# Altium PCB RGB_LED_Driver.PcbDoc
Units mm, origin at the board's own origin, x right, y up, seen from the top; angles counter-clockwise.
Board outline 103.1 x 80.1 mm, 4 copper layers (Top Layer 1, GND, POWER, Bottom Layer 1), stack 1.586 mm thick; 81 components, 62 nets, 264 pads, 168 vias.
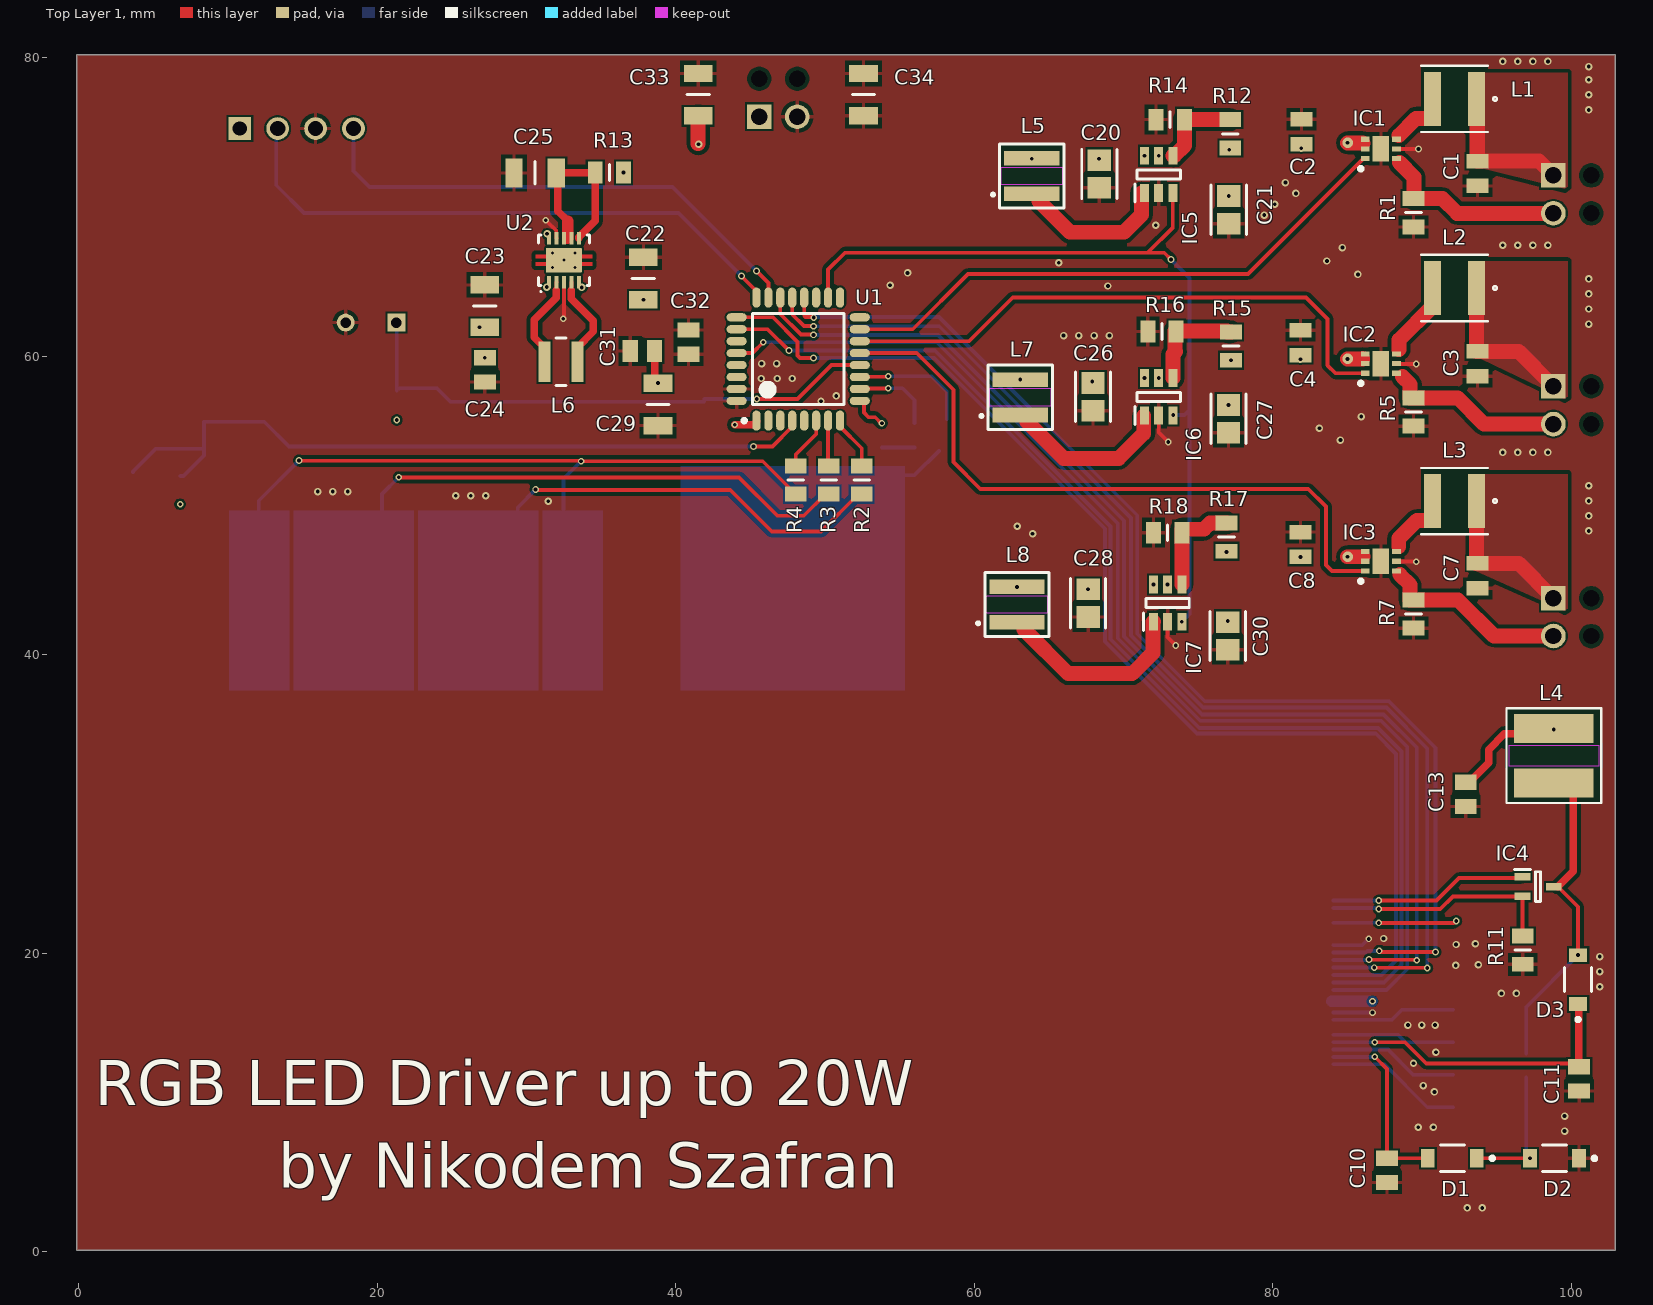
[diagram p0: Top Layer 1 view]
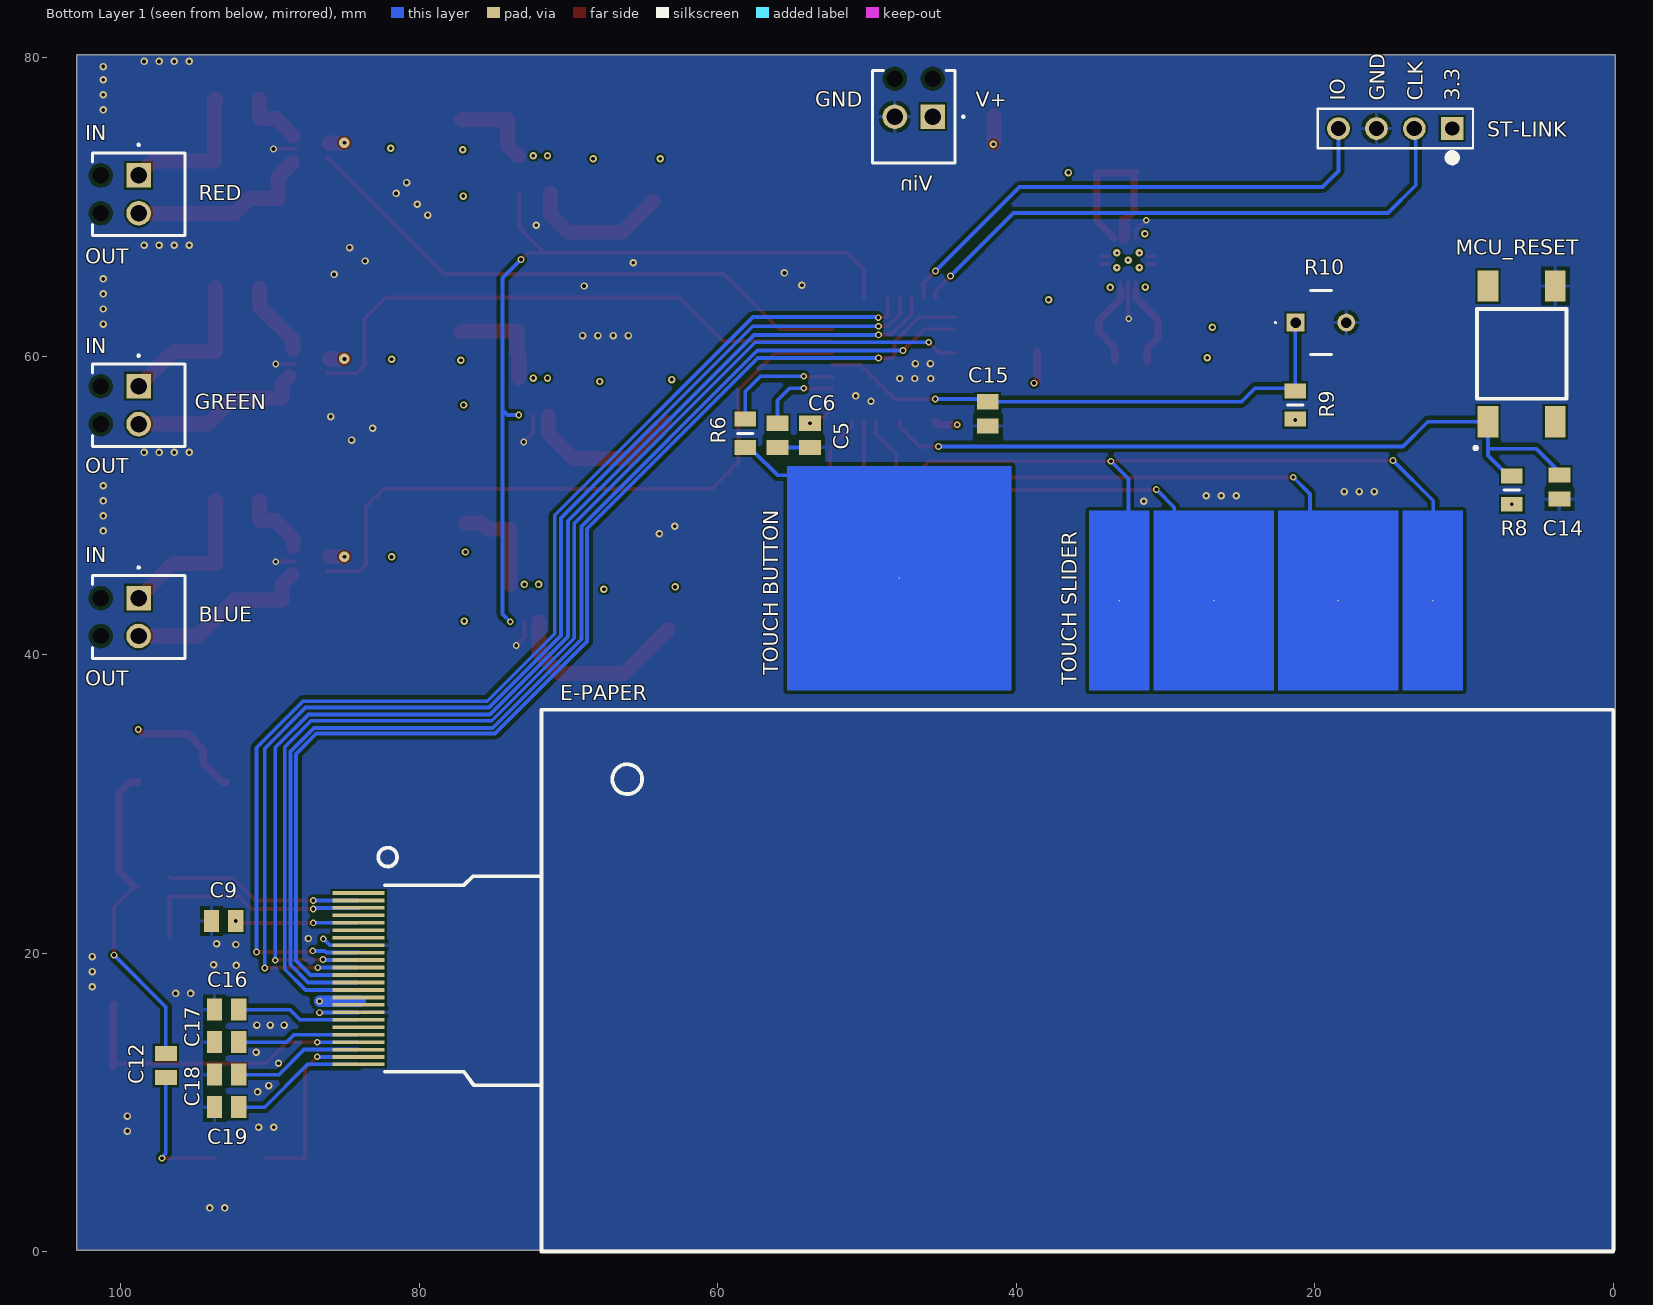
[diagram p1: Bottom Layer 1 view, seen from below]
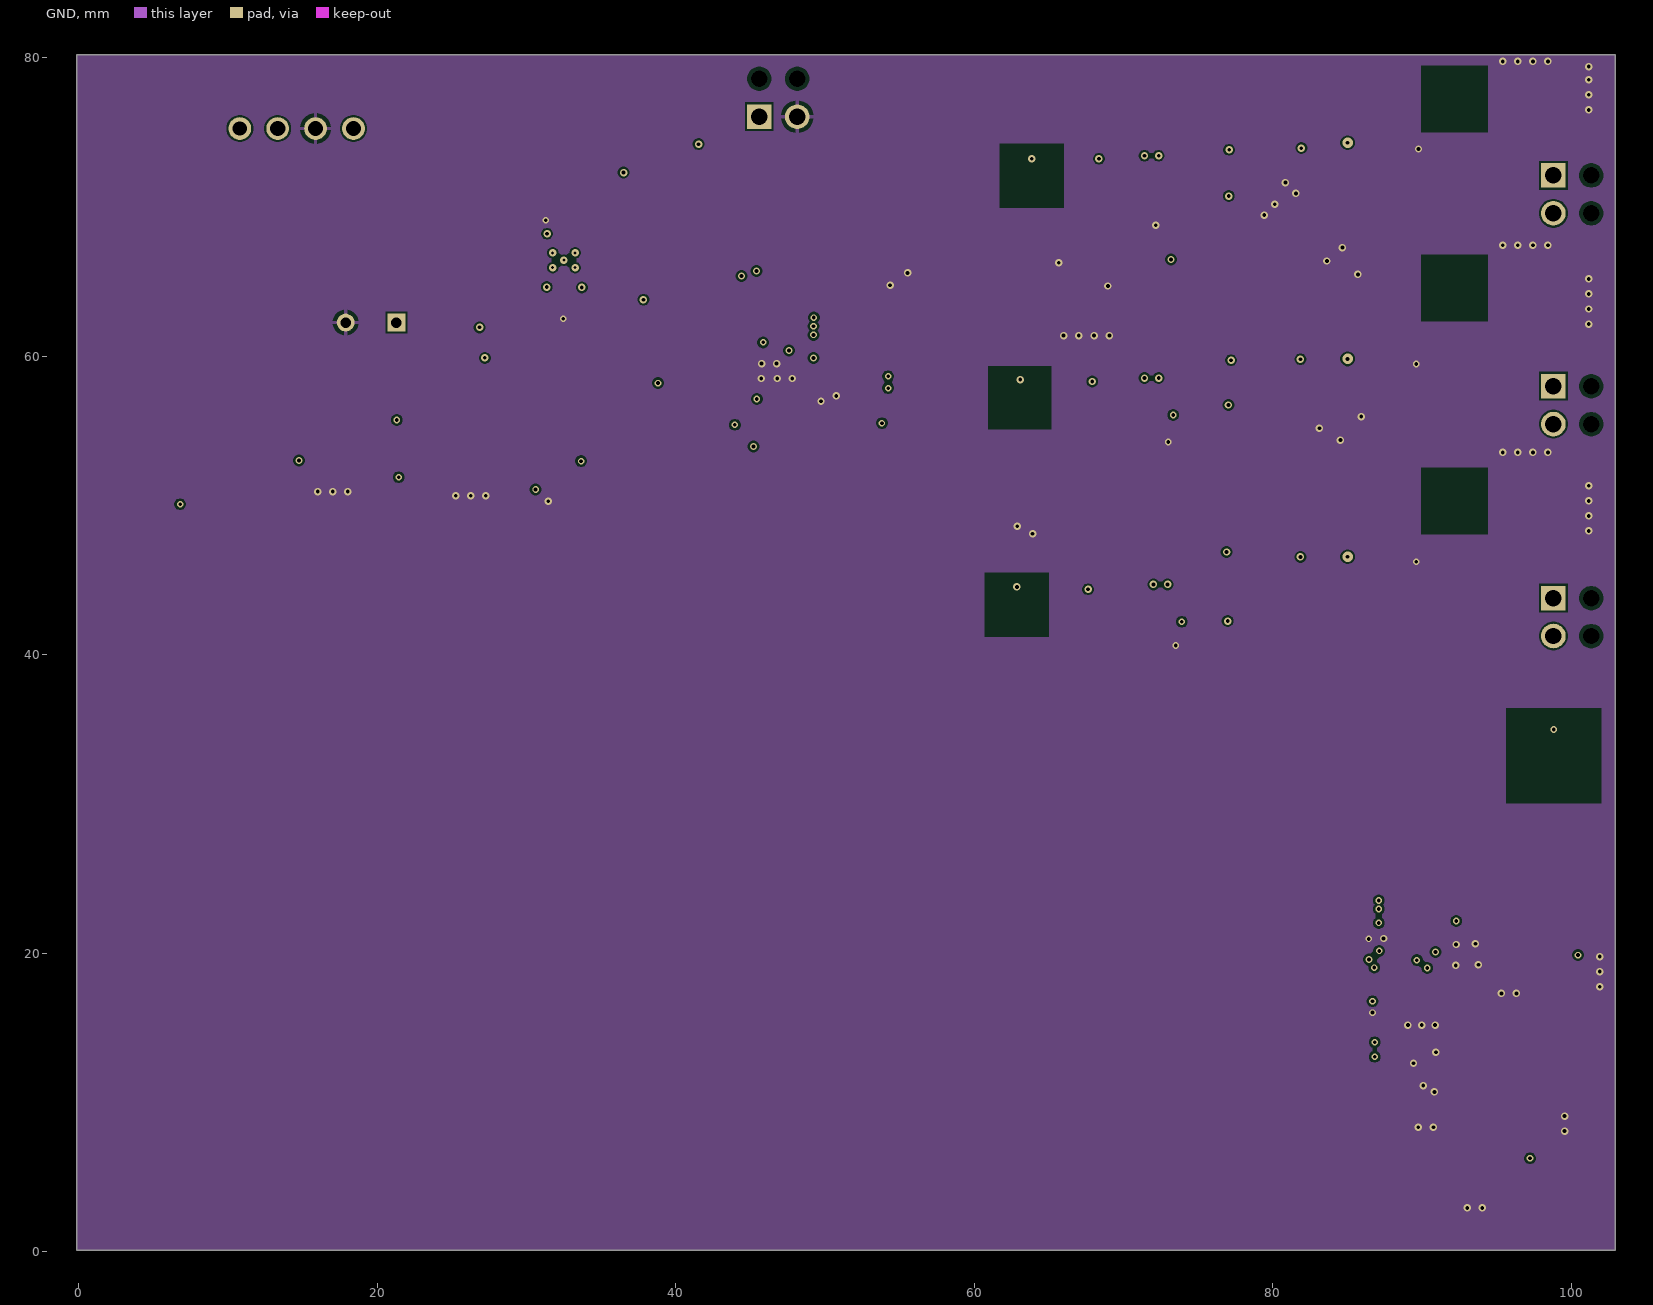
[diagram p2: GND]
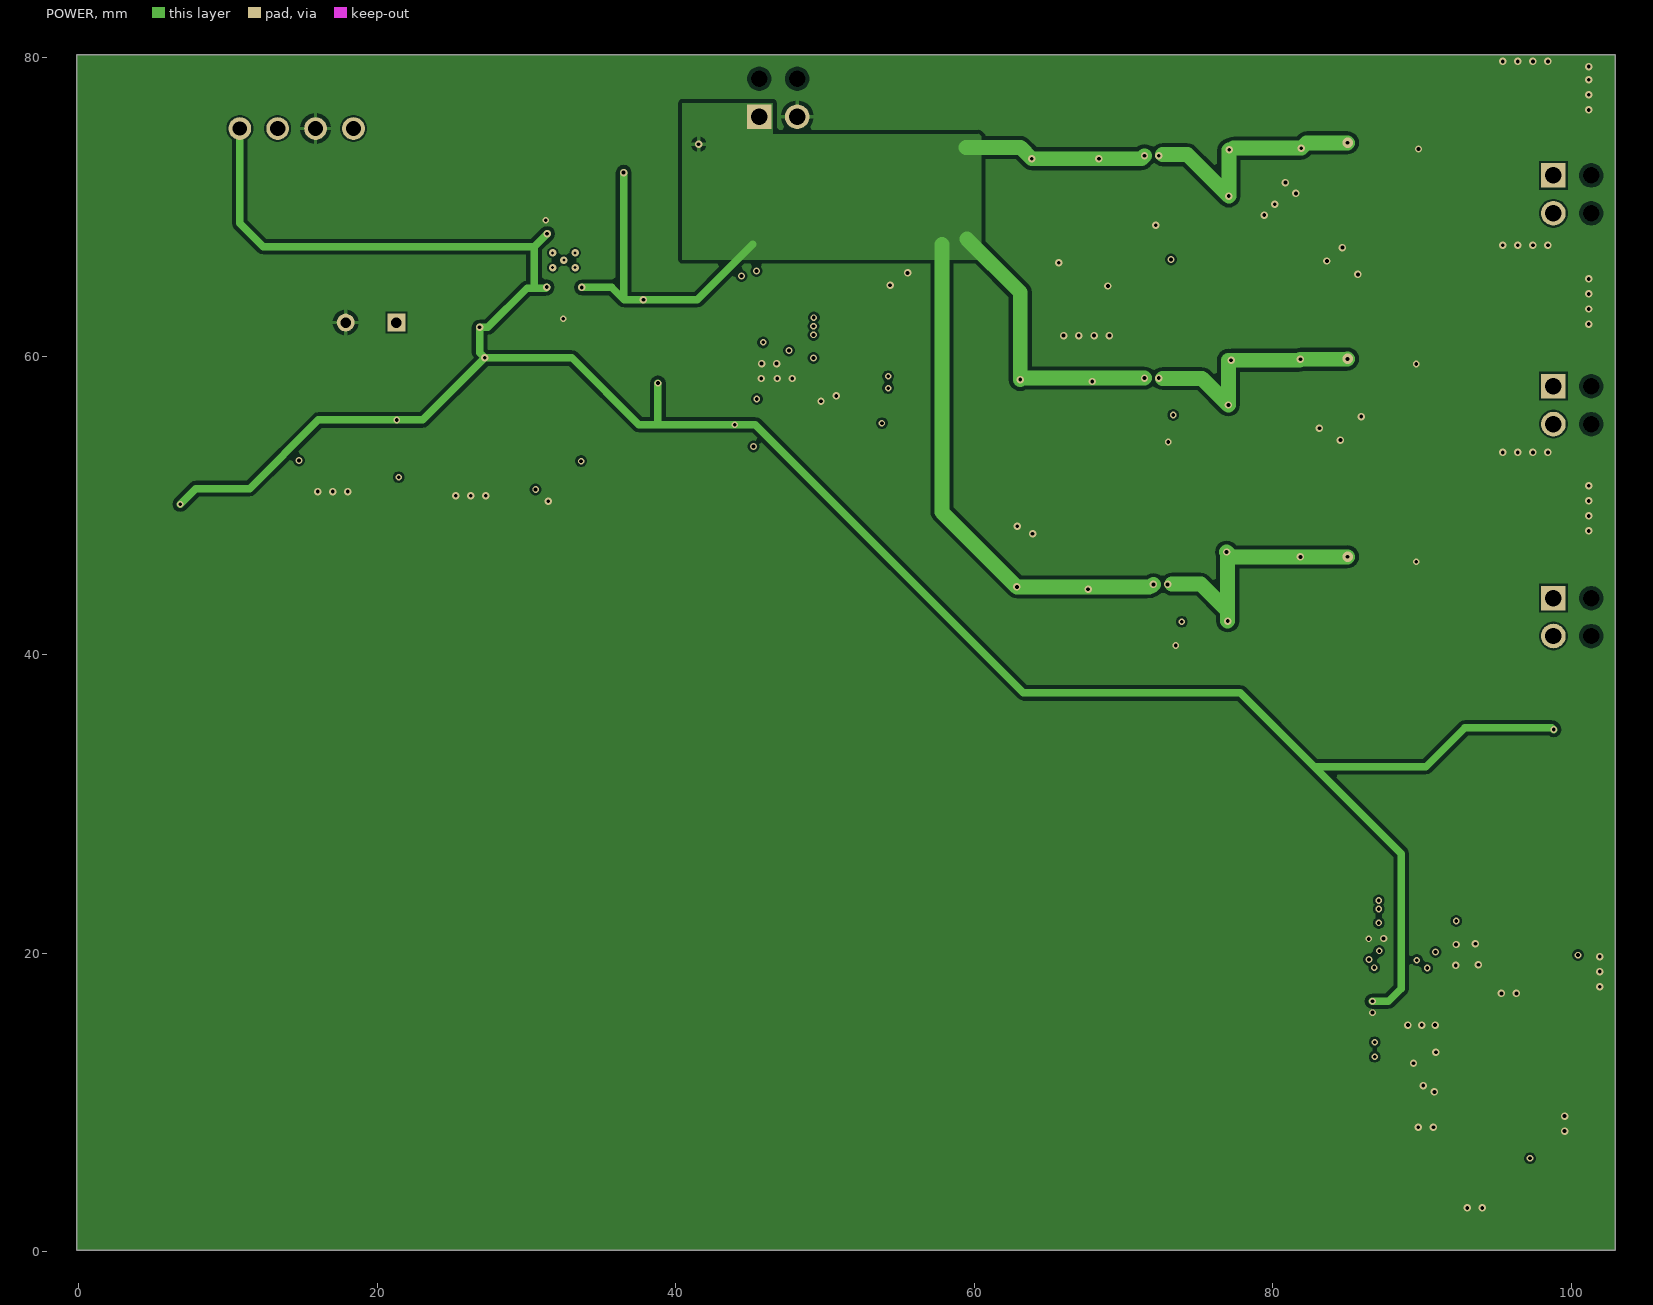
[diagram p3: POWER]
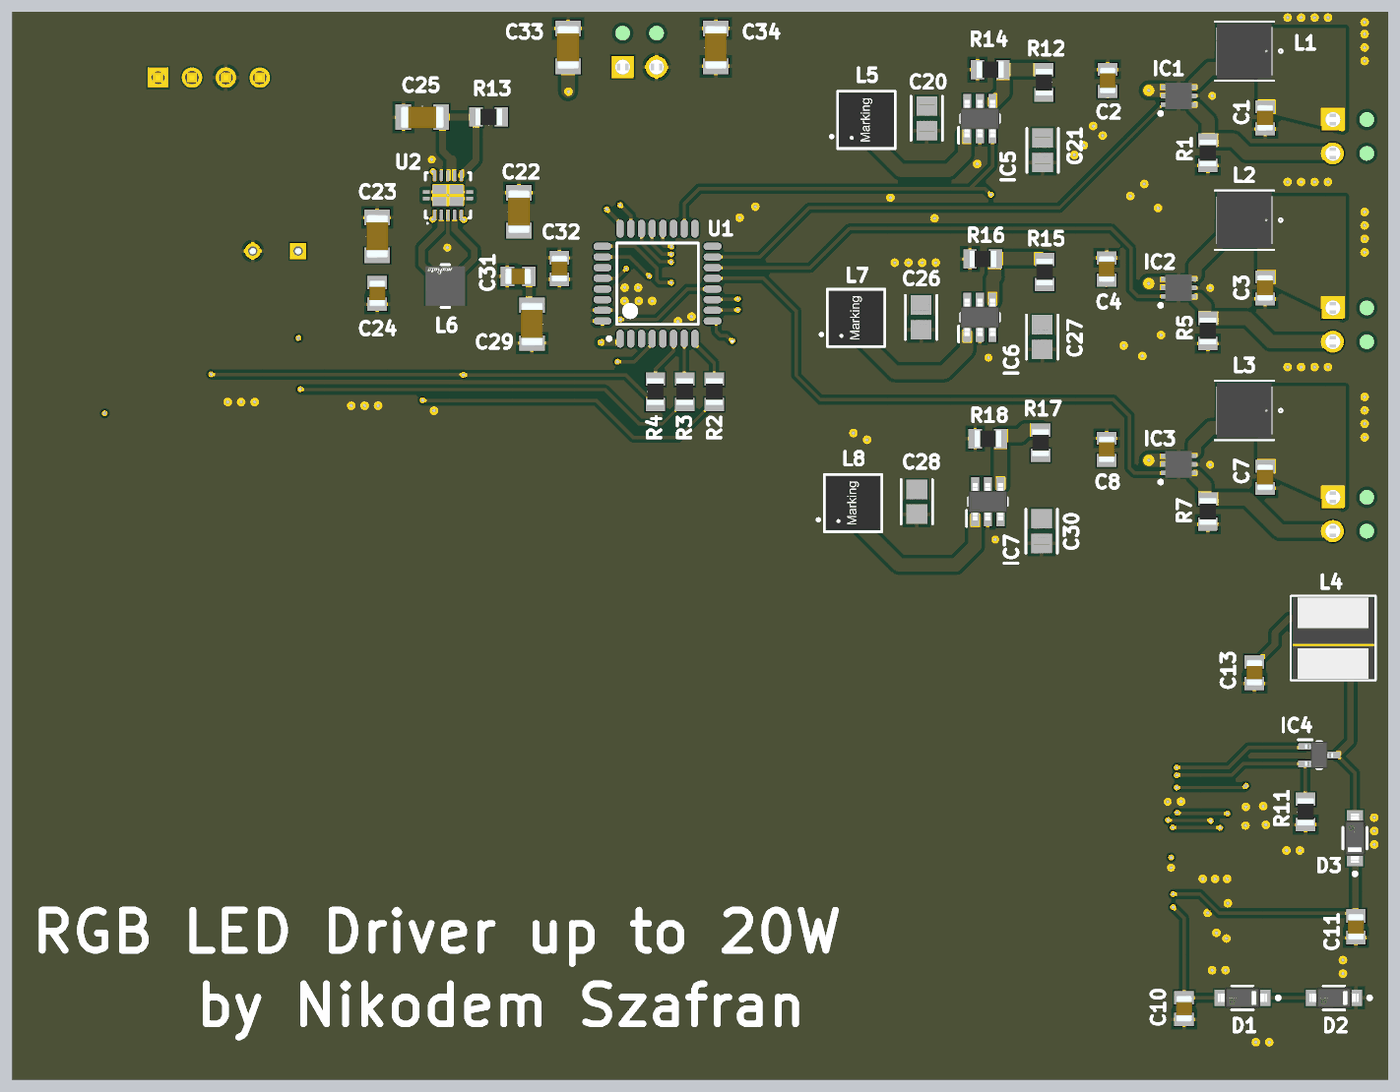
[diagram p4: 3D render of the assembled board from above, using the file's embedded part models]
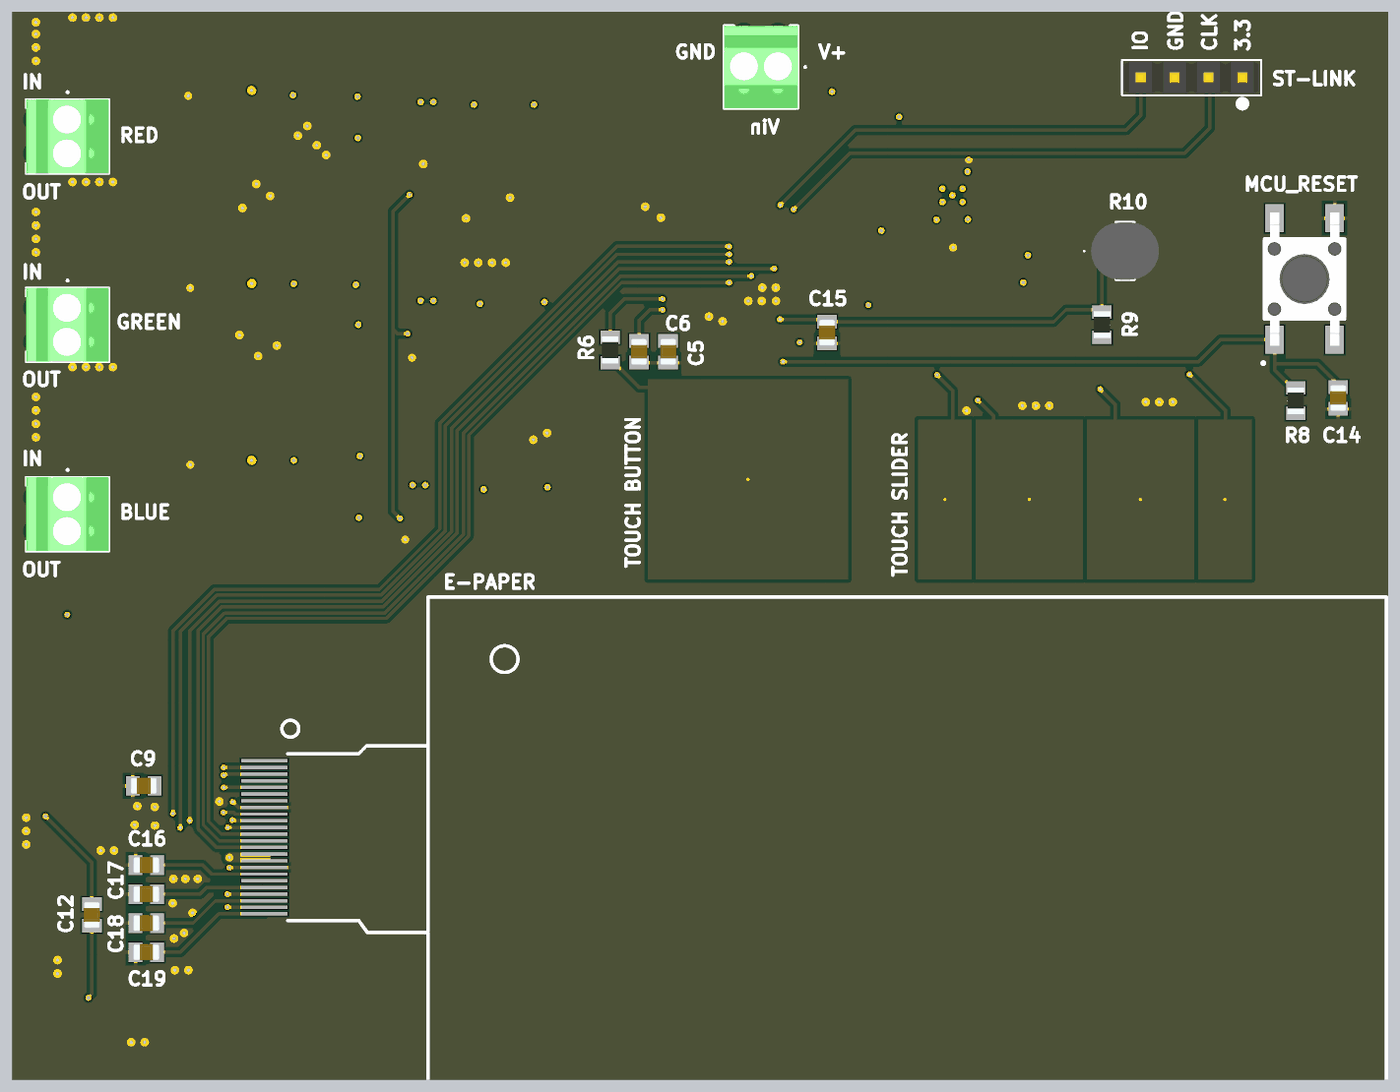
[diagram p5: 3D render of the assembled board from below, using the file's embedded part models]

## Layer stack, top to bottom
Top Solder: solder mask 0.0102, Solder Resist, Dk 3.5
Top Layer 1: signal copper 0.035
Dielectric 2: prepreg 0.2104, PP-006, Dk 4.1
GND: signal copper 0.0152
Dielectric 1: dielectric 1.065, FR-4, Dk 4.6
POWER: signal copper 0.0152
Dielectric 3: prepreg 0.2104, PP-006, Dk 4.1
Bottom Layer 1: signal copper 0.035
Bottom Solder: solder mask 0.0102, Solder Resist, Dk 3.5

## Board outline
-0.14,0.122 102.96,0.122 102.96,80.222 -0.14,80.222

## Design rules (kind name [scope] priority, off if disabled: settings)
Clearance [All] p1: gap=0.127 ignorepadtopadclearanceinfootprint=FALSE except(0.254: Arc-Fill Arc-Poly Arc-Region Track-Fill Track-Poly Track-Region Fill-Fill Fill-Poly Fill-Region Fill-Hole Poly-Poly Poly-Region Poly-Hole Region-Region Region-Hole)
HoleSize [All] p1: absolutevalues=TRUE maxlimit=2.54 minlimit=0.2 maxpercent=80.000 minpercent=20.000
HoleToHoleClearance [All] p1: gap=0.25 allowstackedmicrovias=TRUE
MinimumSolderMaskSliver [All] p1: minsoldermaskwidth=0.05
PolygonConnect PolygonConnect_7 [InNet('LED_R_IN') vs IsNamedPolygon('LED_R_IN_L01_P042')] p1: thpad.connectstyle=Direct thpad.reliefconductorwidth=0.254 thpad.reliefentries=4 thpad.polygonreliefangle="90 Angle" thpad.airgapwidth=0.254 smdpad.connectstyle=Direct smdpad.reliefconductorwidth=0.254 smdpad.reliefentries=4 smdpad.polygonreliefangle="90 Angle" smdpad.airgapwidth=0.254 via.connectstyle=Relief via.reliefconductorwidth=0.254 via.reliefentries=4 via.polygonreliefangle="90 Angle" via.airgapwidth=0.254
PolygonConnect PolygonConnect_6 [InNet('LED_G_IN') vs IsNamedPolygon('LED_G_IN_L01_P044')] p2: thpad.connectstyle=Direct thpad.reliefconductorwidth=0.254 thpad.reliefentries=4 thpad.polygonreliefangle="90 Angle" thpad.airgapwidth=0.254 smdpad.connectstyle=Direct smdpad.reliefconductorwidth=0.254 smdpad.reliefentries=4 smdpad.polygonreliefangle="90 Angle" smdpad.airgapwidth=0.254 via.connectstyle=Relief via.reliefconductorwidth=0.254 via.reliefentries=4 via.polygonreliefangle="90 Angle" via.airgapwidth=0.254
PolygonConnect PolygonConnect_5 [InNet('LED_B_IN') vs IsNamedPolygon('LED_B_IN_L01_P045')] p3: thpad.connectstyle=Direct thpad.reliefconductorwidth=0.254 thpad.reliefentries=4 thpad.polygonreliefangle="90 Angle" thpad.airgapwidth=0.254 smdpad.connectstyle=Direct smdpad.reliefconductorwidth=0.254 smdpad.reliefentries=4 smdpad.polygonreliefangle="90 Angle" smdpad.airgapwidth=0.254 via.connectstyle=Relief via.reliefconductorwidth=0.254 via.reliefentries=4 via.polygonreliefangle="90 Angle" via.airgapwidth=0.254
PolygonConnect PolygonConnect_4 [InNet('Vin') vs IsNamedPolygon('VIN_L03_P039')] p4: thpad.connectstyle=Direct thpad.reliefconductorwidth=0.254 thpad.reliefentries=4 thpad.polygonreliefangle="90 Angle" thpad.airgapwidth=0.254 smdpad.connectstyle=Direct smdpad.reliefconductorwidth=0.254 smdpad.reliefentries=4 smdpad.polygonreliefangle="90 Angle" smdpad.airgapwidth=0.254 via.connectstyle=Relief via.reliefconductorwidth=0.254 via.reliefentries=4 via.polygonreliefangle="90 Angle" via.airgapwidth=0.254
PolygonConnect PolygonConnect_3 [InNet('GND') vs IsNamedPolygon('GND_L03_P041') Or IsNamedPolygon('GND_L04_P040')] p5: thpad.connectstyle=Relief thpad.reliefconductorwidth=0.254 thpad.reliefentries=4 thpad.polygonreliefangle="90 Angle" thpad.airgapwidth=0.254 smdpad.connectstyle=Relief smdpad.reliefconductorwidth=0.254 smdpad.reliefentries=4 smdpad.polygonreliefangle="90 Angle" smdpad.airgapwidth=0.254 via.connectstyle=Direct via.reliefconductorwidth=0.254 via.reliefentries=4 via.polygonreliefangle="90 Angle" via.airgapwidth=0.254
PolygonConnect PolygonConnect_2 [InNet('GND') vs IsNamedPolygon('GND_L02_P043')] p6: thpad.connectstyle=Relief thpad.reliefconductorwidth=0.254 thpad.reliefentries=4 thpad.polygonreliefangle="90 Angle" thpad.airgapwidth=0.254 smdpad.connectstyle=Relief smdpad.reliefconductorwidth=0.254 smdpad.reliefentries=4 smdpad.polygonreliefangle="90 Angle" smdpad.airgapwidth=0.254 via.connectstyle=Direct via.reliefconductorwidth=0.254 via.reliefentries=4 via.polygonreliefangle="90 Angle" via.airgapwidth=0.254
PolygonConnect PolygonConnect_1 [InNet('GND') vs IsNamedPolygon('GND_L01_P046')] p7: thpad.connectstyle=Relief thpad.reliefconductorwidth=0.254 thpad.reliefentries=4 thpad.polygonreliefangle="90 Angle" thpad.airgapwidth=0.254 smdpad.connectstyle=Relief smdpad.reliefconductorwidth=0.254 smdpad.reliefentries=4 smdpad.polygonreliefangle="90 Angle" smdpad.airgapwidth=0.254 via.connectstyle=Direct via.reliefconductorwidth=0.254 via.reliefentries=4 via.polygonreliefangle="90 Angle" via.airgapwidth=0.254
PolygonConnect [All] p8: connectstyle=Relief reliefconductorwidth=0.254 reliefentries=4 polygonreliefangle="90 Angle" airgapwidth=0.254
RoutingVias [All] p1: holewidth=0.254 width=0.45 viastyle="Through Hole" minholewidth=0.2 minwidth=0.45 maxholewidth=0.4 maxwidth=0.65
SilkToSolderMaskClearance [IsPad] p1: minsilkscreentomaskgap=0.15 clearancetoexposedcopper=TRUE
SolderMaskExpansion [All] p1: expansion=0.07 istentingtop=FALSE
SupplyNets "Schematic Supply Nets_1" [InNet('GND')] p1: voltage=0.000
Width [All] p1: maxlimit=8 minlimit=0.102 preferedwidth=1 toplayer_maxwidth=1 toplayer_prefwidth=0.254 midlayer1_maxwidth=1 midlayer1_prefwidth=0.254 bottomlayer_maxwidth=1 bottomlayer_prefwidth=0.254 minimp=50.000000 maximp=50.000000 favimp=50.000000
26 further rules are at their usual default settings.

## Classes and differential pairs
component class logika_sch_ideowy: BLUE C1 C2 C3 C4 C5 C6 C7 C8 C9 C10 C11 C12 C13 C14 C15 C16 C17 C18 C19 D1 D2 D3 E-PAPER GREEN IC1 IC2 IC3 IC4 L1 L2 L3 L4 MCU_RESET R1 R2 R3 R4 R5 R6 R7 R8 R9 R10 R11 RED ST-LINK "TOUCH BUTTON" "TOUCH SLIDER" U1
component class Designator: C20 C21 C22 C23 C24 C25 C26 C27 C28 C29 C30 C31 C32 C33 C34 IC5 IC6 IC7 l L5 L6 L7 L8 R12 R13 R14 R15 R16 R17 R18 U2 Vin

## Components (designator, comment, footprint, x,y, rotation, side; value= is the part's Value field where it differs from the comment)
BLUE "1725656" 1725656 98.809,43.808 r270 bottom
C1 "GRM21BR71A106KE51L" CAPC2012X145N 93.729,72.256 r270 top
C2 "GRM21BR71A106KE51L" CAPC2012X145N 81.935,75.057 r90 top
C3 "GRM21BR71A106KE51L" CAPC2012X145N 93.729,59.506 r270 top
C4 "GRM21BR71A106KE51L" CAPC2012X145N 81.86,60.921 r90 top
C5 "Capacitor" Capacitor_0805 53.814,54.717 r90 bottom value=47n
C6 "Capacitor" Capacitor_0805 55.992,54.717 r90 bottom value=47n
C7 "GRM21BR71A106KE51L" CAPC2012X145N 93.729,45.307 r270 top
C8 "GRM21BR71A106KE51L" CAPC2012X145N 81.86,47.401 r90 top
C9 "Capacitor" Capacitor_0805 93.11,22.172 r180 bottom value=1u
C10 "Capacitor" Capacitor_0805 87.66,5.462 r90 top value=1u
C11 "Capacitor" Capacitor_0805 100.535,11.597 r270 top value=1u
C12 "Capacitor" Capacitor_0805 96.985,12.487 r270 bottom value=1u
C13 "Capacitor" Capacitor_0805 92.935,30.657 r90 top value=1u
C14 "Capacitor" Capacitor_0805 3.61,51.251 r90 bottom value=47n
C15 "Capacitor" Capacitor_0805 41.91,56.157 r90 bottom value=47n
C16 "Capacitor" Capacitor_0805 92.91,16.231 r180 bottom value=1u
C17 "Capacitor" Capacitor_0805 92.91,14.053 r180 bottom value=1u
C18 "Capacitor" Capacitor_0805 92.91,11.875 r180 bottom value=1u
C19 "Capacitor" Capacitor_0805 92.91,9.697 r180 bottom value=1u
C20 "CL21A106KAYNNNE" FP-CL21-IPC_A 68.385,72.221 r90 top
C21 "CL21A106KAYNNNE" FP-CL21-IPC_A 77.06,69.822 r270 top
C22 "Capacitor" Capacitor_1206 37.835,65.222 r270 top value=10u
C23 "Capacitor" Capacitor_1206 27.213,63.372 r270 top value=10u
C24 "Capacitor" Capacitor_0805 27.21,59.097 r90 top value=10u
C25 "Capacitor" Capacitor_1206 30.585,72.297 r0 top value=0.1u
C26 "CL21A106KAYNNNE" FP-CL21-IPC_A 67.96,57.296 r270 top
C27 "CL21A106KAYNNNE" FP-CL21-IPC_A 77.035,55.822 r270 top
C28 "CL21A106KAYNNNE" FP-CL21-IPC_A 67.635,43.472 r270 top
C29 "Capacitor" Capacitor_1206 38.81,56.792 r270 top value=10u
C30 "CL21A106KAYNNNE" FP-CL21-IPC_A 76.985,41.272 r270 top
C31 "Capacitor" Capacitor_0805 37.77,60.372 r0 top value=100n
C32 "Capacitor" Capacitor_0805 40.86,60.957 r90 top value=100n
C33 "Capacitor" Capacitor_1206 41.507,77.54 r270 top value=10u
C34 "Capacitor" Capacitor_1206 52.581,77.54 r270 top value=10u
D1 "MBR0530" FP-425-04-MFG 92.035,6.272 r180 top
D2 "MBR0530" FP-425-04-MFG 98.885,6.272 r180 top
D3 "MBR0530" FP-425-04-MFG 100.46,18.247 r90 top
E-PAPER "18401 Waveshare" "18401 WAVESHARE" 35.91,18.172 r270 bottom
GREEN "1725656" 1725656 98.809,58.007 r270 bottom
IC1 "TPS92201ADRVR" SON65P200X200X80-7N 87.252,73.907 r0 top
IC2 "TPS92201ADRVR" SON65P200X200X80-7N 87.252,59.521 r0 top
IC3 "TPS92201ADRVR" SON65P200X200X80-7N 87.252,46.272 r0 top
IC4 "SI1304BDL-T1-E3" SOT65P210X110-3N 97.785,24.472 r0 top
IC5 "TLV61070ADBVR" SOT95P280X145-6N 72.36,72.197 r90 top
IC6 "TLV61070ADBVR" SOT95P280X145-6N 72.36,57.297 r90 top
IC7 "" SOT95P280X145-6N 72.96,43.472 r90 top
L1 "SDER041H-2R2MS" IND_SDER041H_CYN 92.18,77.26 r180 top value=2.2uH
L2 "SDER041H-2R2MS" IND_SDER041H_CYN 92.18,64.586 r180 top value=2.2uH
L3 "SDER041H-2R2MS" IND_SDER041H_CYN 92.18,50.311 r180 top value=2.2uH
L4 "SRR5018-470Y" IND_BOURNS_SRR5018 98.835,33.25 r90 top
L5 "74438357022" WE-MAPI_4030 63.86,72.099 r90 top
L6 "LQH3NPN2R2MMEL" FP-LQH3NPH_ME-MFG 32.31,59.647 r180 top
L7 "74438357022" WE-MAPI_4030 63.085,57.262 r90 top
L8 "74438357022" WE-MAPI_4030 62.86,43.372 r90 top
MCU_RESET "FSM4JSMATR" FSM4JSMATR 6.135,60.172 r0 bottom (schematic designator S1)
R1 "Resistor" Resistor_0805 89.437,69.63 r90 top value=75m
R2 "Resistor" Resistor_0805 52.46,51.722 r90 top value=1K (schematic designator R4)
R3 "Resistor" Resistor_0805 50.252,51.722 r90 top value=1K
R4 "Resistor" Resistor_0805 48.044,51.722 r90 top value=1K (schematic designator R2)
R5 "Resistor" Resistor_0805 89.437,56.28 r90 top value=75m
R6 "Resistor" Resistor_0805 58.16,54.847 r90 bottom value=1K
R7 "Resistor" Resistor_0805 89.437,42.742 r90 top value=75m
R8 "Resistor" Resistor_0805 6.796,51.047 r270 bottom value=10K
R9 "Resistor" Resistor_0805 21.31,56.747 r270 bottom value=1.5M
R10 "PGM5659D" PGM5659D 21.285,62.272 r180 bottom
R11 "Resistor" Resistor_0805 96.76,20.222 r90 top value=2.2
R12 "Resistor" Resistor_0805 77.16,74.922 r270 top value=820k
R13 "Resistor" Resistor_0805 35.56,72.322 r0 top value=100
R14 "Resistor" Resistor_0805 73.135,75.872 r0 top value=82k
R15 "Resistor" Resistor_0805 77.21,60.697 r270 top value=820k
R16 "Resistor" Resistor_0805 72.585,61.672 r0 top value=82k
R17 "Resistor" Resistor_0805 76.91,47.897 r270 top value=820k
R18 "Resistor" Resistor_0805 72.96,48.197 r0 top value=82k
RED "1725656" 1725656 98.809,72.129 r270 bottom
ST-LINK "77311-118-04LF" 77311-118-04LF_AMP 10.79,75.272 r180 bottom
"TOUCH BUTTON" "QTouch Button" ?#1 47.835,45.147 r180 bottom (schematic designator CS2)
"TOUCH SLIDER" "Small QTouch Slider" ?#2 22.596,43.647 r0 bottom (schematic designator CS1)
U1 "STM32F051K6T6" STM-LQFP32_L 48.21,59.822 r90 top
U2 "TPS63001DRCT" DRC0010J_V 32.51,66.447 r90 top
Vin "1725656" 1725656 45.596,76.066 r0 bottom

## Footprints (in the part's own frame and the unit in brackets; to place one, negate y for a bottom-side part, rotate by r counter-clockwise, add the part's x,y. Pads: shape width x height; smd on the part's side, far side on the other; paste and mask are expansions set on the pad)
"18401 WAVESHARE" [mm] "2.66 inch e-Paper display. Display resolution 296*152px"
  rect 0.25x3.5 smd: 1(-5.881,-48.16) 2(-5.381,-48.16) 3(-4.881,-48.16) 4(-4.381,-48.16) 5(-3.881,-48.16) 6(-3.381,-48.16) 7(-2.881,-48.16) 8(-2.381,-48.16) 9(-1.881,-48.16) 10(-1.381,-48.16) 11(-0.881,-48.16) 12(-0.381,-48.16) 13(0.119,-48.16) 14(0.619,-48.16) 15(1.119,-48.16) 16(1.619,-48.16) 17(2.119,-48.16) 18(2.619,-48.16) 19(3.119,-48.16) 20(3.619,-48.16) 21(4.119,-48.16) 22(4.619,-48.16) 23(5.111,-48.16) 24(5.6,-48.16)
  silkscreen extent -18.15,-46.84 18.15,35.91
77311-118-04LF_AMP [mil]
  rect 60x60 / inner round 60 / far side rect 60x60 hole 38 paste-99999 mask+0: 1(0,0)
  round 60 hole 40 paste-99999 mask+0: 2(-100,0) 3(-200,0) 4(-300,0)
  silkscreen extent -355,-87 55,52, body extent -350,-47 50,47, height 350
1725656 [mm]
  rect 1.65x1.65 hole 1.1: 1(0,0)
  round 1.65 hole 1.1: 2(2.54,0)
  round 0.55 hole 1.1 unplated: MH1(0,-2.54) MH2(2.54,-2.54)
  silkscreen extent -2.1,-3.1 4.04,3.1, body extent -1.5,-3.1 4.04,3.1, height 9
Capacitor_0805 [mm] "CAPC2012X152N"
  rect 1.02x1.47 smd: 1(-0.81,0) 2(0.81,0)
  body extent -1,-0.63 1,0.63, height 1.52
Capacitor_1206 [mm] "CAPC3317X180N,  / footprint from 1206GC102KAT1A"
  rect 1.17x1.92 smd: 1(-1.42,0) 2(1.42,0)
  silkscreen extent 0,-0.75 0,0.75, body extent -1.65,-0.85 1.65,0.85, height 1.8
CAPC2012X145N [mm]
  rect 0.97x1.47 smd: 1(-0.83,0) 2(0.83,0)
  body extent -1,-0.63 1,0.63, height 1.45
DRC0010J_V [mm] "SON, 10-Leads, Body 3x3mm, Pitch 0.5mm, Thermal Pad 2.4x1.65mm, TI Recommended"
  rrect36% 0.85x0.28 smd paste-0.025 mask+0.07: 1(-1.475,1) 2(-1.475,0.5) 3(-1.475,0) 4(-1.475,-0.5) 5(-1.475,-1) 6(1.475,-1) 7(1.475,-0.5) 8(1.475,0) 9(1.475,0.5) 10(1.475,1)
  rrect6% 1.65x2.4 smd paste-0.825 mask+0.07: 11(0,0)
  Top Layer 1 region: -0.39,1.2 -0.11,1.2 -0.11,1.9 -0.39,1.9
  Top Layer 1 region: 0.39,1.9 0.11,1.9 0.11,1.2 0.39,1.2
  Top Layer 1 region: 0.39,-1.2 0.11,-1.2 0.11,-1.9 0.39,-1.9
  Top Layer 1 region: -0.39,-1.9 -0.11,-1.9 -0.11,-1.2 -0.39,-1.2
  silkscreen extent -2.15,-1.7 1.7,1.7, body extent -1.55,-1.55 1.55,1.55, height 1
FP-425-04-MFG [mil]
  rect 36x48 smd paste+0 mask+0: 1(-64.5,0) 2(64.5,0)
  silkscreen extent -110,-35 32,35, body extent -72,-31 72,31, height 53
FP-CL21-IPC_A [mm]
  rect 1.455x1.556 smd paste+0 mask+0: 1(-0.926,0) 2(0.926,0)
  silkscreen extent -1.65,-1.18 1.65,1.18, body extent -2.15,-1.28 2.15,1.28, height 0.25
FP-LQH3NPH_ME-MFG [mm]
  rect 0.8x2.7 smd paste+0 mask+0: 1(-1.1,0) 2(1.1,0)
  silkscreen extent -0.33,-1.6 0.33,1.6, body extent -1.7,-1.7 1.7,1.7, height 0.25
FSM4JSMATR [mm]
  rect 1.4x2.1 smd: 1(2.25,4.55) 2(2.25,-4.55) 3(-2.25,4.55) 4(-2.25,-4.55)
  silkscreen extent -3,-3 3.18,6.39, body extent -3,-5 3,5, height 5.13
IND_BOURNS_SRR5018 [mil]
  rect 76x209 smd paste+0 mask+0: 1(-72,0) 2(72,0)
  Top Layer 1 keep-out region: -27.5,-118 -27.5,118 27.5,118 27.5,-118
  silkscreen extent -125,-125 125,125, body extent -120,-120 120,120, height 79
IND_SDER041H_CYN [mil]
  rect 45x142 smd paste-22.5 mask+0: 1(-58.07,0) 2(58.07,0)
  silkscreen extent -112,-88 88,88, body extent -83,-83 83,83, height 71
PGM5659D [mm]
  rect 1.2x1.2 hole 0.7: 1(0,0)
  round 1.2 hole 0.7: 2(3.4,0)
  silkscreen extent -1.4,-2.15 2.4,2.15, body extent -0.84,-2.15 4.24,2.15, height 2.5
Resistor_0805 [mm] "RESC2012X60N, / footprint from CRCW08050000Z0EAHP"
  rect 1x1.45 smd: 1(-0.95,0) 2(0.95,0)
  silkscreen extent 0,-0.53 0,0.53, body extent -1,-0.63 1,0.63, height 0.6
SON65P200X200X80-7N [mm]
  rect 0.6x0.35 smd: 1(-1.05,-0.65) 2(-1.05,0) 3(-1.05,0.65) 4(1.05,0.65) 5(1.05,0) 6(1.05,-0.65)
  rect 1.1x1.7 smd: 7(0,0)
  silkscreen extent -1.47,-1.45 -1.22,-1.2, body extent -1,-1 1,1, height 0.8
SOT65P210X110-3N [mm]
  rect 1.05x0.5 smd: 1(-1.05,0.65) 2(-1.05,-0.65) 3(1.05,0)
  silkscreen extent -1.58,-1 0.18,1.15, body extent -1.05,-1 1.05,1, height 1.1
SOT95P280X145-6N [mm]
  rect 1.2x0.6 smd: 1(-1.25,0.95) 2(-1.25,0) 3(-1.25,-0.95) 4(1.25,-0.95) 5(1.25,0) 6(1.25,0.95)
  silkscreen extent -1.85,-1.45 0.3,1.6, body extent -1.4,-1.45 1.4,1.45, height 1.2
STM-LQFP32_L [mm] "QFP, 32-Leads, Body 7x7mm, Pitch 0.8mm, IPC High Density"
  oval 1.35x0.55 smd: 1(-4.125,2.8) 2(-4.125,2) 3(-4.125,1.2) 4(-4.125,0.4) 5(-4.125,-0.4) 6(-4.125,-1.2) 7(-4.125,-2) 8(-4.125,-2.8) 17(4.125,-2.8) 18(4.125,-2) 19(4.125,-1.2) 20(4.125,-0.4) 21(4.125,0.4) 22(4.125,1.2) 23(4.125,2) 24(4.125,2.8)
  oval 0.55x1.35 smd: 9(-2.8,-4.125) 10(-2,-4.125) 11(-1.2,-4.125) 12(-0.4,-4.125) 13(0.4,-4.125) 14(1.2,-4.125) 15(2,-4.125) 16(2.8,-4.125) 25(2.8,4.125) 26(2,4.125) 27(1.2,4.125) 28(0.4,4.125) 29(-0.4,4.125) 30(-1.2,4.125) 31(-2,4.125) 32(-2.8,4.125)
  silkscreen extent -4.25,-3.05 3.05,3.75, body extent -3.5,-3.5 3.5,3.5, height 1.6
WE-MAPI_4030 [mm] "SMT Shielded Power Inductor, body 4.1x4.1mm"
  rect 0.98x3.7 smd: 1(-1.185,0) 2(1.185,0)
  Top Layer 1 keep-out region: -0.595,2.05 0.595,2.05 0.595,-2.05 -0.595,-2.05
  silkscreen extent -2.15,-2.15 2.15,2.7, body extent -2.05,-2.05 2.05,2.05, height 3.1
?#1 [mm]
  round 0.1 smd paste-0.05: 1(0,0)
  Top Layer 1 region: -7.5,-7.5 -7.5,7.5 7.5,7.5 7.5,-7.5 -7.5,-7.5
?#2 [mm]
  round 0.1 smd paste-0.05: 1(-10.492,0) 1(10.492,0) 2(-4.167,0) 3(4.167,0)
  Top Layer 1 region: -12.5,6 -8.483,6 -8.483,-6 -12.5,-6 -12.5,6
  Top Layer 1 region: -8.183,6 -0.15,6 -0.15,-6 -8.183,-6 -8.183,6
  Top Layer 1 region: 0.15,6 8.183,6 8.183,-6 0.15,-6 0.15,6
  Top Layer 1 region: 8.483,6 12.5,6 12.5,-6 8.483,-6 8.483,6

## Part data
BLUE GREEN RED Vin: "2-pin screw terminal block Connector", Manufacturer_Name="Phoenix Contact", Mouser Part Number=651-1725656
C1 C2 C3 C4 C7 C8: "Capacitor, LED DRIVER", Capacitance=10uF, Manufacturer_Name="Murata Electronics", Mouser Part Number=81-GRM21BR71A106KE51
C9 C10 C11 C12 C17 C18 C19: "Capacitor X5R/X7R, 25V"
C13 C16: "Capacitor X5R/X7R, 6V/25V"
C20 C21 C26 C27 C28 C30: library part CMP-13271-002975-1, "CL21 Series 0805 10uF 25V ±10% Tolerance X5R Multilayer Ceramic Chip Capacitor", Capacitance=10uF, Case Code (Imperial)=0805, Case Code (Metric)=2012, Dielectric=X5R, Max Operating Temperature=85°C, Min Operating Temperature=-55°C, Package Quantity=1, Tolerance=10%, Voltage Rating=25V
D1 D2 D3: library part 1d6ec82d83fb6aee721767c19dac4b9, "DIODE SCHOTTKY 30V 500MA SOD123", Average Rectified Current=500mA, Forward Voltage=430mV, Max Forward Surge Current (Ifsm)=5.5A, Max Operating Temperature=150°C, Max Repetitive Reverse Voltage (Vrrm)=30V, Max Reverse Leakage Current=130uA, Min Operating Temperature=-65°C, Package Quantity=1
E-PAPER: "E-PAPER display", MPN=18401
IC1 IC2 IC3: "Integrated Circuit", Manufacturer_Name="Texas Instruments", Mouser Part Number=595-TPS92201ADRVR
IC4: "Integrated Circuit", Manufacturer_Name=Vishay, Mouser Part Number=781-SI1304BDL-E3
IC5 IC6: "Integrated Circuit", Manufacturer_Name="Texas Instruments", Mouser Part Number=595-TLV61070ADBVR
IC7: library part TLV61070ADBVR, "Integrated Circuit", Manufacturer_Name="Texas Instruments", Mouser Part Number=595-TLV61070ADBVR
L1 L2 L3: "Inductor, LED Driver", Mfr_Name=Cyntec
L4: "Inductor", Mfr_Name="Bourns Electronics"
L5 L7 L8: library part CMP-03913-81252529-2, "74438357022 Fixed Ind 2.2UH 5.2A 26 Mohm SMD", Ambient Temperature Range High=85°C, Ambient Temperature Range Low=-40°C, Current Rating=5.2A, DC Resistance (DCR)=22mΩ, Inductance=2.2µH, Inductance Tolerance=20%, Max Operating Temperature=125°C, Saturation Current=7A, Self Resonant Frequency=35MHz, Series Resistance=26mΩ, Test Frequency=100kHz
L6: library part CMP-06042-009066-1, "Wire Wound Ferrite Inductor for Power Lines 2.2μH ±20% 0.078Ω 2100mA 1212", Case Code (Imperial)=1212, Case Code (Metric)=3030, Current Rating=2.1A, DC Resistance (DCR)=78mR, Inductance=2.2uH, Max Operating Temperature=85°C, Min Operating Temperature=-40°C, Resistor Type=Wirewound, Saturation Current=1.8A, Self Resonant Frequency=60MHz, Test Frequency=1MHz, Tolerance=20%
MCU_RESET: "Switch", Manufacturer_Name="TE Connectivity", Mouser Part Number=506-FSM4JSMATR
R1 R5 R7: "Rsense"
R10: "Resistor", Manufacturer_Name="TOKEN ELECTRONICS INDUSTRY CO LTD"
R11: "Resistor 0805 1%"
ST-LINK: "4-pin male goldpin header", Mfr_Name="Amphenol ICC"
"TOUCH BUTTON": library part QTouchButton
"TOUCH SLIDER": library part SmallQTouchSlider
U1: library part CMP-0304-00023-2, "ARM Cortex-M0 32-bit MCU, 32 KB Flash, 4 KB Internal RAM, 25 I/Os, 32-pin LQFP, -40 to 85 degC, Tray", I/Os (High Current)=25, Operating Frequency(F) (Processor speed) (MHz)=48, Supply Voltage(Vcc) min (V)=2
U2: library part CMP-0345-00002-2, "Buck-Boost Voltage Converter with 1.8 to 5.5 V Input and 3.3 V Output, -40 to 85 degC, 10-Pin SON (DRC), Green (RoHS & no Sb/Br)", Dynamic Voltage Scaling=TRUE, Manufacturer="Texas Instruments", Switching Frequency(Max)(kHz)=1500

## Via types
v1: diameter 0.5, hole 0.254, Top Layer 1 to Bottom Layer 1, 111 vias
v2: diameter 0.45, hole 0.254, Top Layer 1 to Bottom Layer 1, 49 vias
v3: diameter 0.5, hole 0.2, Top Layer 1 to Bottom Layer 1, 5 vias
v4: diameter 0.7, hole 0.254, Top Layer 1 to Bottom Layer 1, 3 vias

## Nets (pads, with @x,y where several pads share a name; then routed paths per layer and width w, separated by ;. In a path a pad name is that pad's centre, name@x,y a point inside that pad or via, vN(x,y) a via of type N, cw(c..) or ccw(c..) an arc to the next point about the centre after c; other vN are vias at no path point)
ADC_FOTORESISTOR: C15.2 R9.1 R10.1 U1.12 | length 36.8
  Top Layer 1 w0.254: v2(45.435,57.147) 48.16,57.147 50.447,59.434 52.322,59.434 U1.12
  Bottom Layer 1 w0.254: R10.1 21.31,62.247 R9.1 ; R9.1@21.442,57.829 21.485,57.872 24.01,57.872 24.915,56.967 C15.2 ; C15.2@41.91,57.147 v2(45.435,57.147)
BUSY: E-PAPER.9 U1.20 | length 80.8
  Top Layer 1 w0.254: U1.20 48.61,62.721 48.693,62.638 49.216,62.638 v2(49.254,62.601) ; v2(87.135,20.172) 87.188,20.172 87.263,20.097 v2(90.91,20.097)
  Bottom Layer 1 w0.254: v2(49.254,62.601) 49.292,62.638 49.44,62.638 49.449,62.647 57.635,62.647 70.926,49.356 70.926,41.422 75.451,36.897 87.799,36.897 90.91,33.786 v2(90.91,20.097) ; E-PAPER.9 86.236,20.053 86.356,20.172 v2(87.135,20.172)
BUTTON_SAMP: C6.2 U1.10 | length 5.5
  Top Layer 1 w0.254: U1.10 52.36,57.847 54.21,57.847 v2(54.235,57.872)
  Bottom Layer 1 w0.254: v2(54.235,57.872) 55.185,57.872 55.992,57.065 C6.2
D/C#: E-PAPER.11 U1.21 | length 81.4
  Top Layer 1 w0.254: U1.21 47.81,62.822 48.585,62.047 49.212,62.047 v2(49.235,62.024) ; v2(86.81,19.047) 86.823,19.034 90.348,19.034 v2(90.36,19.022)
  Bottom Layer 1 w0.254: v2(49.235,62.024) 57.658,62.024 70.502,49.18 70.502,41.307 75.337,36.473 87.623,36.473 90.36,33.736 v2(90.36,19.022) ; E-PAPER.11 84.072,19.051 86.806,19.051 v2(86.81,19.047)
GDR: E-PAPER.2 IC4.1 | length 13.3
  Top Layer 1 w0.254: v2(87.11,23.547) 90.985,23.547 92.485,25.047 96.66,25.047 IC4.1
  Bottom Layer 1 w0.254: E-PAPER.2 84.072,23.551 87.106,23.551 v2(87.11,23.547)
GND: C1.2 C2.2 C3.2 C4.2 C5.1 C6.1 C7.2 C8.2 C9.1 C10.1 C11.2 C13.1 C14.1 C15.1 C16.1 C17.1 C18.1 C19.1 C20.1 C21.2 C22.1 C23.1 C24.1 C25.1 C26.2 C27.2 C28.2 C29.2 C30.2 C31.1 C32.1 C32.2 C33.1 C34.1 C34.2 D2.1 E-PAPER.8 E-PAPER.17 IC1.5 IC1.7 IC2.5 IC2.7 IC3.5 IC3.7 IC5.2 IC6.2 IC7.2 MCU_RESET.4 R1.1 R5.1 R7.1 R10.2 R11.1 R14.1 R16.1 R18.1 ST-LINK.3 U1.31 U1.32 U2.3 U2.9 Vin.2 | length 19.3
  Top Layer 1 w0.254: v2(31.296,69.132) 31.997,68.431 31.997,67.935 U2.9 ; v2@32.506,62.57 v2(32.465,62.528) 32.465,62.581 32.506,62.623 32.506,64.968 U2.3 ; IC6.2 72.36,54.916 v2(73.003,54.273) ; IC7.2 72.96,41.184 v2(73.511,40.633) ; IC3.5 88.315,46.259 89.602,46.259 v2(89.615,46.247) ; IC2.5 88.323,59.5 v2(89.62,59.5) ; IC1.5 v2(89.767,73.907)
  Bottom Layer 1 w0.254: C5.1 C6.1 ; E-PAPER.17 84.072,16.051 86.667,16.051 v2(86.685,16.032) ; E-PAPER.8 84.072,20.555 86.002,20.555 86.421,20.974 v2(86.44,20.974)
  other v1: 93.035,2.947 94.043,2.947 99.56,8.097 89.76,8.347 90.768,8.347 99.56,9.105 90.835,10.722 90.085,11.147 89.435,12.647 90.935,13.372 89.06,15.197 89.985,15.197 90.885,15.197 95.327,17.322 96.335,17.322 101.91,17.772 101.91,18.78 92.26,19.197 93.785,19.247 101.91,19.788 92.285,20.597 93.585,20.647 87.432,20.999 63.91,48.122 101.185,48.306 62.885,48.622 101.185,49.314 31.46,50.297 101.185,50.322 25.26,50.672 26.268,50.672 27.276,50.672 16.01,50.947 17.018,50.947 18.026,50.947 101.185,51.33 95.419,53.572 96.427,53.572 97.435,53.572 98.443,53.572 84.535,54.397 83.135,55.184 85.935,55.972 49.735,56.997 50.76,57.355 45.735,58.522 46.81,58.522 47.81,58.522 45.752,59.522 46.76,59.522 65.985,61.397 67.01,61.397 68.035,61.397 69.06,61.397 101.185,62.172 101.185,63.18 101.185,64.188 68.96,64.722 54.36,64.772 101.185,65.196 85.71,65.497 55.535,65.597 65.66,66.272 83.635,66.397 84.673,67.297 95.419,67.447 96.427,67.447 97.435,67.447 98.443,67.447 72.16,68.797 79.435,69.472 80.143,70.197 81.56,70.922 80.852,71.647 101.185,76.522 101.185,77.53 101.185,78.538 101.185,79.422 95.419,79.772 96.427,79.772 97.435,79.772 98.443,79.772
LED_B_IN: BLUE.1 C7.1 L3.1 | length 10.3
  Top Layer 1 w1: L3.1 93.655,46.152 93.67,46.137 C7.1 96.481,46.137 BLUE.1
LED_B_OUT: BLUE.2 IC3.6 R7.2 | length 12.6
  Top Layer 1 w1: 88.522,45.383 89.212,44.694 89.212,43.692 R7.2 92.408,43.692 94.831,41.268 BLUE.2
LED_G_IN: C3.1 GREEN.1 L2.1 | length 10.4
  Top Layer 1 w1: L2.1 93.655,60.351 93.67,60.336 C3.1 96.481,60.336 GREEN.1
LED_G_OUT: GREEN.2 IC2.6 R5.2 | length 12
  Top Layer 1 w1: 88.688,58.655 89.212,58.13 89.212,57.23 R5.2 92.398,57.23 94.161,55.467 GREEN.2
LED_R_IN: C1.1 L1.1 RED.1 | length 9.7
  Top Layer 1 w1: L1.1 93.727,77.189 93.727,75.104 93.729,75.101 C1.1 97.852,73.086 RED.1
LED_R_OUT: IC1.6 R1.2 RED.2 | length 12.6
  Top Layer 1 w1: 88.497,72.993 89.462,72.028 89.462,70.58 R1.2 91.367,70.58 92.358,69.589 RED.2
MCU_RESET: C14.2 MCU_RESET.1 R8.1 U1.4 | length 50.9
  Top Layer 1 w0.254: v2(45.21,53.972) 46.485,53.972 47.81,55.297 U1.4
  Bottom Layer 1 w0.254: C14.2@3.636,52.267 3.636,52.292 5.166,53.822 8.385,53.822 ; R8.1 7.021,51.997 8.385,53.361 8.385,53.822 ; v2(45.21,53.972) 14.085,53.972 12.435,55.622 MCU_RESET.1 8.385,53.822
NetC12_1: C12.1 D3.2 IC4.3 L4.1 | length 21.8
  Top Layer 1 w0.254: IC4.3 99.11,24.472 100.46,23.122 v2(100.46,19.885)
  Top Layer 1 w0.5: L4.1@98.835,31.497 99.382,31.497 100.135,30.744 100.135,25.497 IC4.3@99.11,24.472
  Bottom Layer 1 w0.254: C12.1 96.985,16.41 v2(100.46,19.885)
NetC12_2: C12.2 D1.1 D2.2 | length 9.1
  Top Layer 1 w0.254: D1.1 v2(97.247,6.272)
  Bottom Layer 1 w0.254: C12.2 96.985,6.587 97.247,6.325 v2(97.247,6.272)
NetC25_2: C25.2 R13.1 U2.6 U2.7 U2.8 | length 12.2
  Top Layer 1 w0.5: 32.769,69.081 32.11,69.741 32.11,72.192 C25.2 32.03,72.322 R13.1 34.61,69.087 33.51,67.987 U2.6
  Top Layer 1 w0.75: 32.769,67.913 32.769,69.081
NetIC1_4: IC1.4 L1.2 | length 4
  Top Layer 1 w1: 88.446,74.796 89.607,75.957 90.634,75.957 90.705,76.028 L1.2
NetIC2_4: IC2.4 L2.2 | length 5
  Top Layer 1 w1: 88.472,60.471 88.472,61.12 90.705,63.354 L2.2
NetIC3_4: IC3.4 L3.2 | length 4.6
  Top Layer 1 w1: 88.446,47.263 88.446,47.796 89.657,49.007 90.634,49.007 90.705,49.079 L3.2
NetIC5_1: IC5.1 L5.1 | length 9.7
  Top Layer 1 w1: 64.325,70.412 66.415,68.322 70.035,68.322 71.21,69.497 IC5.1@71.21,70.947
NetIC5_4: IC5.4 R12.1 R14.2 | length 5.9
  Top Layer 1 w1: IC5.4 73.41,73.447 74.085,74.122 R14.2 R12.1
NetIC6_1: IC6.1 L7.1 | length 10.7
  Top Layer 1 w1: L7.1@63.55,55.612 65.99,53.172 69.685,53.172 71.36,54.847 IC6.1@71.36,55.997
NetIC6_4: IC6.4 R15.1 R16.2 | length 7
  Top Layer 1 w1: IC6.4 73.31,60.147 73.485,60.322 73.46,60.347 73.46,61.697 76.935,61.697 76.985,61.647 R15.1
NetIC7_1: IC7.1 L8.1 | length 12.5
  Top Layer 1 w1: L8.1@63.343,41.704 66.3,38.747 70.585,38.747 71.985,40.147 71.985,42.197 IC7.1
NetIC7_4: IC7.4 R17.1 R18.2 | length 6.9
  Top Layer 1 w1: IC7.4 R18.2 73.91,48.422 75.385,48.422 75.81,48.847 R17.1
NetL6_1: L6.1 U2.4 | length 6.4
  Top Layer 1 w0.254: 33.01,64.447 U2.4
  Top Layer 1 w0.5: 33.01,64.447 33.01,63.872 34.485,62.397 34.485,61.672 33.41,60.597 L6.1
NetL6_2: L6.2 U2.2 | length 6.2
  Top Layer 1 w0.254: 32.002,64.447 32.002,64.964 U2.2
  Top Layer 1 w0.5: L6.2 31.21,60.597 30.535,61.272 30.535,62.472 32.002,63.939 32.002,64.447
NetR2_1: "TOUCH SLIDER.3" R2.1 | length 27
  Top Layer 1 w0.254: v2(30.613,51.083) 30.638,51.058 43.649,51.058 46.435,48.272 49.735,48.272 52.235,50.772 R2.1
  Bottom Layer 1 w0.254: 28.959,48.787 29.413,49.24 29.413,49.883 v2(30.613,51.083)
NetR3_1: "TOUCH SLIDER.2" R3.1 | length 33.3
  Top Layer 1 w0.254: v2(21.438,51.908) 21.463,51.883 44.249,51.883 46.81,49.322 48.577,49.322 50.027,50.772 R3.1
  Bottom Layer 1 w0.254: 20.313,49.533 20.313,50.783 v2(21.438,51.908)
NetR4_1: "TOUCH SLIDER.1" R4.1 | length 46
  Top Layer 1 w0.254: v2(14.763,53.033) 14.788,53.008 33.638,53.008 v2(33.663,52.983) 45.833,52.983 R4.1
  Bottom Layer 1 w0.254: 11.865,48.965 12.063,49.162 12.063,50.333 v2(14.763,53.033) ; 12.19,47.706 12.19,49.164 ; 32.488,48.456 32.488,51.808 v2(33.663,52.983)
NetR6_1: "TOUCH BUTTON.1" R6.1 | length 3.9
  Bottom Layer 1 w0.254: 54.41,51.997 54.46,52.047 56.01,52.047 R6.1@57.635,53.672
PWM_B: IC3.1 U1.13 | length 45
  Top Layer 1 w0.254: U1.13 56.153,60.222 58.61,57.764 58.61,52.922 60.41,51.122 82.385,51.122 83.569,49.938 83.569,46.018 83.965,45.622 IC3.1
PWM_G: IC2.1 U1.14 | length 39
  Top Layer 1 w0.254: U1.14 59.66,61.022 62.585,63.947 82.235,63.947 83.671,62.511 83.671,59.404 84.204,58.871 IC2.1
PWM_R: IC1.1 U1.15 | length 38.6
  Top Layer 1 w0.254: U1.15 55.885,61.822 59.585,65.522 78.342,65.522 86.077,73.257 IC1.1
RES#: E-PAPER.10 U1.22 | length 80.2
  Top Layer 1 w0.254: U1.22 47.01,62.847 48.385,61.472 49.21,61.472 v2(49.235,61.447) ; v2(86.46,19.599) 86.486,19.573 89.634,19.573 v2(89.66,19.547)
  Bottom Layer 1 w0.254: v2(49.235,61.447) 57.585,61.447 70.043,48.989 70.043,41.228 75.258,36.013 87.433,36.013 89.66,33.786 v2(89.66,19.547) ; E-PAPER.10 86.361,19.553 86.407,19.599 v2(86.46,19.599)
RESE: E-PAPER.3 IC4.2 R11.2 | length 15.7
  Top Layer 1 w0.254: v2(87.11,22.97) 91.233,22.97 92.085,23.822 IC4.2 96.735,21.197 R11.2
  Bottom Layer 1 w0.254: E-PAPER.3 86.974,23.053 87.057,22.97 v2(87.11,22.97)
SLIDER_SAMP: C5.2 U1.9 | length 2.5
  Top Layer 1 w0.254: U1.9 52.471,57.022 52.608,56.885 52.608,56.234 52.918,55.924 53.364,55.924 53.761,55.527 v2(53.814,55.527)
SPI_MISO: U1.27
SPI_MOSI: E-PAPER.14 U1.28 | length 81.4
  Top Layer 1 w0.254: U1.28 45.135,60.222 v2(45.86,60.947)
  Bottom Layer 1 w0.254: v2(45.86,60.947) 57.485,60.947 69.618,48.814 69.618,41.114 75.143,35.589 87.257,35.589 89.022,33.824 89.022,18.945 87.629,17.553 E-PAPER.14
SPI_NSS: E-PAPER.12 U1.25 | length 79.7
  Top Layer 1 w0.254: U1.25 46.51,62.622 48.16,60.972 48.16,60.072 48.335,59.897 v2(49.235,59.897)
  Bottom Layer 1 w0.254: v2(49.235,59.897) 57.321,59.897 68.76,48.458 68.76,40.894 74.924,34.731 86.901,34.731 88.26,33.372 88.26,19.522 87.291,18.553 E-PAPER.12
SPI_SCK: E-PAPER.13 U1.26 | length 80.1
  Top Layer 1 w0.254: U1.26 46.16,61.822 v2(47.585,60.397)
  Bottom Layer 1 w0.254: v2(47.585,60.397) 57.36,60.397 69.141,48.616 69.141,41.052 75.082,35.112 87.059,35.112 88.641,33.53 88.641,19.239 87.454,18.053 E-PAPER.13
SWDCLK: ST-LINK.2 U1.24 | length 39.4
  Top Layer 1 w0.254: v2(44.41,65.397) 44.41,65.372 45.41,64.372 U1.24
  Bottom Layer 1 w0.254: ST-LINK.2 13.235,75.177 13.235,71.472 15.096,69.611 40.196,69.611 v2(44.41,65.397)
SWDIO: ST-LINK.4 U1.23 | length 34.7
  Top Layer 1 w0.254: v2(45.41,65.722) 46.21,64.922 U1.23
  Bottom Layer 1 w0.254: ST-LINK.4 18.41,72.422 19.485,71.347 39.785,71.347 v2(45.41,65.722)
TSC_BUTTON: R6.2 U1.11 | length 8.1
  Top Layer 1 w0.254: U1.11 52.36,58.647 54.21,58.647 v2(54.235,58.672)
  Bottom Layer 1 w0.254: v2(54.235,58.672) 57.135,58.672 58.16,57.647 R6.2
TSC_SLIDER1: R4.2 U1.6 | length 3.6
  Top Layer 1 w0.254: R4.2 48.044,53.422 49.41,54.788 U1.6
TSC_SLIDER2: R3.2 U1.7 | length 3
  Top Layer 1 w0.254: U1.7 50.21,52.714 R3.2
TSC_SLIDER3: R2.2 U1.8 | length 3.6
  Top Layer 1 w0.254: U1.8 51.01,55.297 52.46,53.847 R2.2
TSCL: E-PAPER.6
TSDA: E-PAPER.7
V3.3: C13.2 C23.2 C24.2 C29.1 C31.2 E-PAPER.15 E-PAPER.16 L4.2 R8.2 R9.2 ST-LINK.1 U1.1 U2.1 U2.10 | length 183.9
  Top Layer 1 w0.5: C31.2@38.58,60.347 38.58,58.442 v2(38.81,58.212) ; v2(43.96,55.422) 45.185,55.422 U1.1@45.435,55.672 ; C13.2 93.16,31.467 94.472,32.779 94.472,33.654 95.524,34.706 98.539,34.706 v2(98.835,35.002)
  POWER w0.5: v2(6.796,50.097) 7.846,51.147 11.46,51.147 16.06,55.747 v2(21.31,55.747) 23.05,55.747 v1(27.21,59.907) ; ST-LINK.1 10.79,68.917 12.36,67.347 30.51,67.347 ; v1(31.36,64.647) 31.285,64.572 30.51,64.572 ; v1(31.385,68.222) 30.51,67.347 ; v2(38.81,58.212) 38.81,55.422 ; v2(86.685,16.797) 87.76,16.797 88.61,17.647 88.61,26.672 82.773,32.509 ; v2(98.835,35.002) 98.715,35.122 92.885,35.122 90.273,32.509 82.773,32.509 ; v1(27.21,59.907) 26.86,60.257 v1(26.86,61.952) 27.415,61.952 30.035,64.572 30.51,64.572 ; v1(27.21,59.907) 33.05,59.907 37.535,55.422 38.81,55.422 ; 30.51,64.572 30.51,67.347 ; 38.81,55.422 v2(43.96,55.422) 45.337,55.422 63.3,37.458 77.824,37.458 82.773,32.509
  Bottom Layer 1 w0.75: 83.96,16.797 v2(86.685,16.797)
V5.5_1: C2.1 C21.1 IC1.2 IC1.3 IC5.5 R12.2 | length 17.6
  Top Layer 1 w1: v4(85.017,74.314) 86.033,74.314 86.059,74.288
  POWER w1: 72.61,73.522 74.286,73.522 v1(77.06,70.748) 77.06,73.822 v1(77.085,73.847) ; 77.375,73.957 v1(81.92,73.957) 82.277,74.314 v4(85.017,74.314)
  other v1: 72.36,73.447
V5.5_2: C4.1 C27.1 IC2.2 IC2.3 IC6.5 R15.2 | length 16.9
  Top Layer 1 w1: v4(85.017,59.836) 86.008,59.836 86.033,59.861
  POWER w1: 72.61,58.522 75.261,58.522 v1(77.035,56.748) v1@77.035,59.747 ; v1(77.21,59.747) v1@81.795,59.747 ; v1(81.86,59.812) 84.993,59.812 v4(85.017,59.836)
  other v1: 72.36,58.547
V5.5_3: C8.1 C30.1 IC3.2 IC3.3 IC7.5 R17.2 | length 18.1
  Top Layer 1 w1: v4(85.017,46.577) 86.033,46.577 86.059,46.602
  POWER w1: 73.235,44.747 75.185,44.747 76.985,42.947 ; v1(76.91,46.897) 77.236,46.571 v1(81.86,46.571) 85.012,46.571 v4(85.017,46.577) ; v1(76.985,42.272) 76.985,42.947 ; 76.985,46.622 76.985,42.947
  other v1: 72.96,44.722
V5.5_EN: IC5.3 IC6.3 IC7.3 U1.18 | length 56.5
  Top Layer 1 w0.254: U1.18 50.21,65.822 51.335,66.947 71.61,66.947 ; v2(73.185,66.497) 72.735,66.947 71.61,66.947 ; IC5.3 73.31,68.647 71.61,66.947
  Bottom Layer 1 w0.254: v2(73.185,66.497) 74.435,65.247 74.435,56.422 ; v2(73.335,56.072) 74.085,56.072 74.435,56.422 ; v2(73.91,42.222) 74.435,42.747 74.435,56.422
VCOM: C19.2 E-PAPER.24 | length 9.2
  Bottom Layer 1 w0.254: E-PAPER.24 87.485,12.572 90.36,9.697 C19.2
VDD: C16.2 E-PAPER.18 | length 8.3
  Bottom Layer 1 w0.254: E-PAPER.18 87.991,15.553 88.669,16.231 C16.2
VGH: C11.1 D3.1 E-PAPER.21 | length 21.4
  Top Layer 1 w0.254: v2(86.835,14.047) 88.86,14.047 90.285,12.622 100.32,12.622 C11.1
  Top Layer 1 w0.5: D3.1 100.498,16.571 100.498,12.444 C11.1
  Bottom Layer 1 w0.254: E-PAPER.21 84.072,14.051 86.831,14.051 v2(86.835,14.047)
VGL: C10.2 D1.2 E-PAPER.23 | length 12.7
  Top Layer 1 w0.254: v2(86.835,13.074) 87.66,12.249 C10.2 D1.2
  Bottom Layer 1 w0.254: E-PAPER.23 84.072,13.063 86.824,13.063 v2(86.835,13.074)
Vin: C20.2 C22.2 C26.1 C28.1 C33.2 IC5.6 IC6.6 IC7.6 L5.2 L7.2 L8.2 R13.2 U2.5 Vin.1 | length 89.6
  Top Layer 1 w0.5: v1@41.507,74.252 v1(41.536,74.223)
  Top Layer 1 w1: v1@41.507,74.252 C33.2
  POWER w0.5: v1(33.71,64.622) 35.715,64.622 36.51,63.827 ; v1(36.51,72.322) 36.51,63.827 ; 45.16,67.522 41.44,63.802 v1(37.835,63.802) 36.535,63.802 36.51,63.827
  POWER w1: 57.835,67.497 57.835,49.582 v1(62.86,44.557) 71.612,44.557 ccw(c71.612,45.12) v1(72.01,44.722) ; 59.444,74.009 63.098,74.009 v1(63.86,73.247) v1(68.359,73.247) 71.21,73.247 v1(71.41,73.447) ; 59.51,67.872 63.085,64.297 v1(63.085,58.447) 63.185,58.547 v1(71.41,58.547)
  other v1: 67.635,44.398 67.91,58.323
VSH1: C17.2 E-PAPER.20 | length 8.2
  Bottom Layer 1 w0.254: E-PAPER.20 88.404,14.553 88.904,14.053 C17.2
VSH2: C9.2 E-PAPER.5 | length 8.3
  Top Layer 1 w0.254: v2(87.11,22.047) 92.122,22.047 92.247,22.172 v2(92.3,22.172)
  Bottom Layer 1 w0.254: E-PAPER.5 84.072,22.051 87.106,22.051 v2(87.11,22.047)
VSL: C18.2 E-PAPER.22 | length 8.7
  Bottom Layer 1 w0.254: E-PAPER.22 87.729,13.553 89.407,11.875 C18.2
pads on no net: BLUE.MH1 BLUE.MH2 E-PAPER.1 E-PAPER.4 E-PAPER.19 GREEN.MH1 GREEN.MH2 MCU_RESET.2 MCU_RESET.3 RED.MH1 RED.MH2 U1.2 U1.3 U1.5 U1.16 U1.17 U1.19 U1.29 U1.30 U2.11 Vin.MH1 Vin.MH2
copper on no net:
  other v3: 31.76,65.947 33.26,65.947 32.51,66.447 31.76,66.947 33.26,66.947

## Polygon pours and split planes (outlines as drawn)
GND on POWER "GND_L03_P041" (solid, remove dead copper, pour order 41): -0.14,0.122 102.96,0.122 102.96,80.222 -0.14,80.222
Vin on POWER "VIN_L03_P039" (solid, remove dead copper, pour order 39): 40.44,66.491 60.485,66.491 60.485,74.923 46.511,74.882 46.511,76.981 40.44,76.981 40.44,72.561
GND on Top Layer 1 "GND_L01_P046" (solid, remove dead copper, pour order 46): -0.14,0.122 102.96,0.122 102.96,80.222 -0.14,80.222
LED_B_IN on Top Layer 1 "LED_B_IN_L01_P045" (solid, remove dead copper, pour order 45): 93.26,52.122 99.761,52.122 99.761,42.856 93.285,45.772
LED_R_IN on Top Layer 1 "LED_R_IN_L01_P042" (solid, remove dead copper, pour order 42): 93.21,78.997 99.761,78.997 99.761,71.177 93.185,72.822
LED_G_IN on Top Layer 1 "LED_G_IN_L01_P044" (solid, remove dead copper, pour order 44): 93.21,66.372 99.761,66.372 99.761,57.055 93.235,60.197
GND on Bottom Layer 1 "GND_L04_P040" (solid, remove dead copper, pour order 40): -0.14,0.122 102.96,0.122 102.96,80.222 -0.14,80.222
GND on GND "GND_L02_P043" (solid, remove dead copper, pour order 43): -0.14,0.122 102.96,0.122 102.96,80.222 -0.14,80.222

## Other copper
Top Layer 1:
  pour cut-out: 89.958,79.483 94.403,79.483 94.404,79.102 89.957,79.06
  pour cut-out: 89.958,66.808 94.403,66.808 94.425,66.428 89.967,66.418
  pour cut-out: 89.958,52.533 94.403,52.533 94.376,52.178 89.96,52.193
  pour cut-out: 89.958,52.533 93.059,52.544 93.108,48.075 89.958,48.088
  pour cut-out: 95.66,36.425 102.01,36.425 102.01,30.075 95.66,30.075
  pour cut-out: 60.71,45.522 65.01,45.522 65.01,41.222 60.71,41.222
  pour cut-out: 65.235,59.412 65.235,55.112 60.935,55.112 60.935,59.412
  pour cut-out: 61.71,74.249 66.01,74.249 66.01,69.949 61.71,69.949
  pour cut-out: 89.958,79.483 93.084,79.483 93.084,75.038 89.958,75.038
  pour cut-out: 89.958,66.808 93.084,66.808 93.084,62.363 89.958,62.363
GND:
  pour cut-out: 89.958,52.533 94.403,52.533 94.403,48.088 89.958,48.088
  pour cut-out: 60.935,59.347 65.17,59.347 65.17,55.112 60.935,55.112
  pour cut-out: 60.71,45.522 65.01,45.522 65.01,41.222 60.71,41.222
  pour cut-out: 95.66,36.425 102.01,36.425 102.01,30.075 95.66,30.075
  pour cut-out: 61.71,74.249 66.01,74.249 66.01,69.949 61.71,69.949
  pour cut-out: 89.958,79.483 94.403,79.483 94.403,75.038 89.958,75.038
  pour cut-out: 89.958,66.808 94.403,66.808 94.403,62.363 89.958,62.363

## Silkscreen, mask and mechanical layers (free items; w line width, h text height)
Top Overlay:
  text "RGB LED Driver up to 20W" at 1.06,9.822 h3
  text "by Nikodem Szafran" at 13.36,4.299 h3
Bottom Overlay:
  text "3.3" at 10.288,77.12 h1 r270
  text "CLK" at 12.778,77.12 h1 r270
  text "GND" at 15.307,77.12 h1 r270
  text "IO" at 17.964,77.12 h1 r270
  text "V+" at 42.706,76.726 h1
  text "GND" at 53.456,76.726 h1
  text "IN" at 102.377,74.476 h1
  text "OUT" at 102.377,66.226 h1
  text "IN" at 102.377,60.226 h1
  text "OUT" at 102.377,52.169 h1
  text "IN" at 102.377,46.226 h1
  text "OUT" at 102.377,37.919 h1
